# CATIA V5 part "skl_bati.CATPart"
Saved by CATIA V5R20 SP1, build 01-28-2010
Part number: skl_bati
Publications: "Plan_ref", "Point_ref", "Plan_symetrie_bati", "Point_ref_bati_a1", "Point_a2", "Plan_symetrie_bati_decale", "Plan_symetrie_bati_decale2", "PointA", "PointD", "axe_pivot_D", "axe_ref", "axe_pivot_A", "Plan_ortho_ref", "Plan_ortho_ref_bis", "Plan_ortho_construction_bati", "Plan_ortho_construction_bati_bis", "Plan_decalage", "axe_coulisseau"
Bounding box of the stored display mesh (mm): x 0 to 40, y -50 to 400, z -220 to 0
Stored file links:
  C:\Users\Fabien-port\Desktop\test\skl_bati.CATPart
  C:\Users\Fabien-port\Desktop\test\ass_skl_mecanisme_a_coulisseau.CATProduct
  C:\Users\Fabien-port\Desktop\test\mecanisme_a_coulisseau.CATProduct
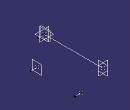
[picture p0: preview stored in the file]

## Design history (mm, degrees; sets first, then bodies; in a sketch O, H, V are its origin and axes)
External parameters (linked from other documents)
  External.epaisseur_bielle = 8 mm
Set1
  Plane1 "Plan_ref": linked copy from another document
  Point1 "Point_ref": linked copy from another document
  Point2 "Point_a2": linked copy from another document
  Point3 "PointA": linked copy from another document
  Point4 "PointD": linked copy from another document
  Line1 "axe_ref": linked copy from another document
  Plane2 "Plan_ortho_ref": linked copy from another document
  Plane3 "Plan_ortho_ref_bis": linked copy from another document
Set2
  Plane4 "Plan_symetrie_bati": type OffsetPt, RefPlane Plane1, RefPoint Point1
  Point5 "Point_ref_bati_a1": (0, 0, 0), relative to Point1
  Plane5 "Plan_symetrie_bati_decale": type OffsetPt, RefPlane Plane1, RefPoint Point2
  Plane6 "Plan_symetrie_bati_decale2": type OffsetPt, RefPlane Plane1, RefPoint Point3
  Point6 "PointD": (0, 0, 0), relative to Point4
  Line2 "axe_pivot_D": type PtDir, RefPoint Point6, Direction Line1, Start 0, End 40
  Line3 "axe_pivot_A": type PtDir, RefPoint Point3, Direction Line1, Start 0, End 40
  Plane7 "Plan_ortho_construction_bati": type Offset, RefPlane Plane2, Offset 0
  Plane8 "Plan_ortho_construction_bati_bis": type Offset, RefPlane Plane3, Offset 0
  Plane9 "Plan_decalage": type Offset, RefPlane Plane4, Offset 9 {= External.epaisseur_bielle +1mm}, reversed
  Line4 "axe_coulisseau": type PtPt, FirstPoint Point1, SecondPoint Point2
Body1 (main body)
